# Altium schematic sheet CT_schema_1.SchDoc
size 532 x 463 mm
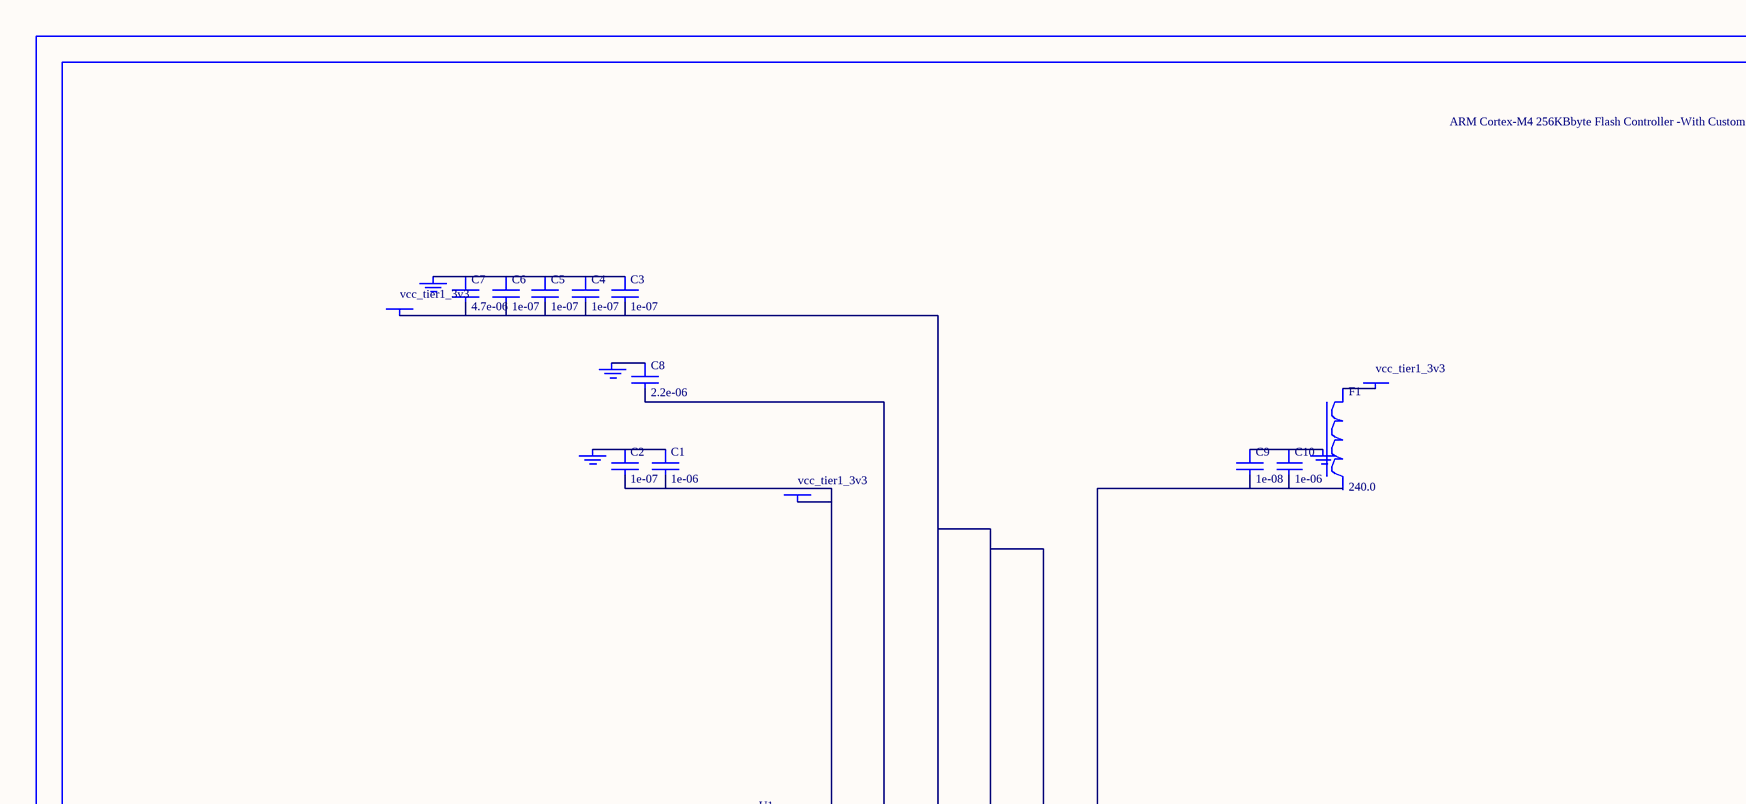
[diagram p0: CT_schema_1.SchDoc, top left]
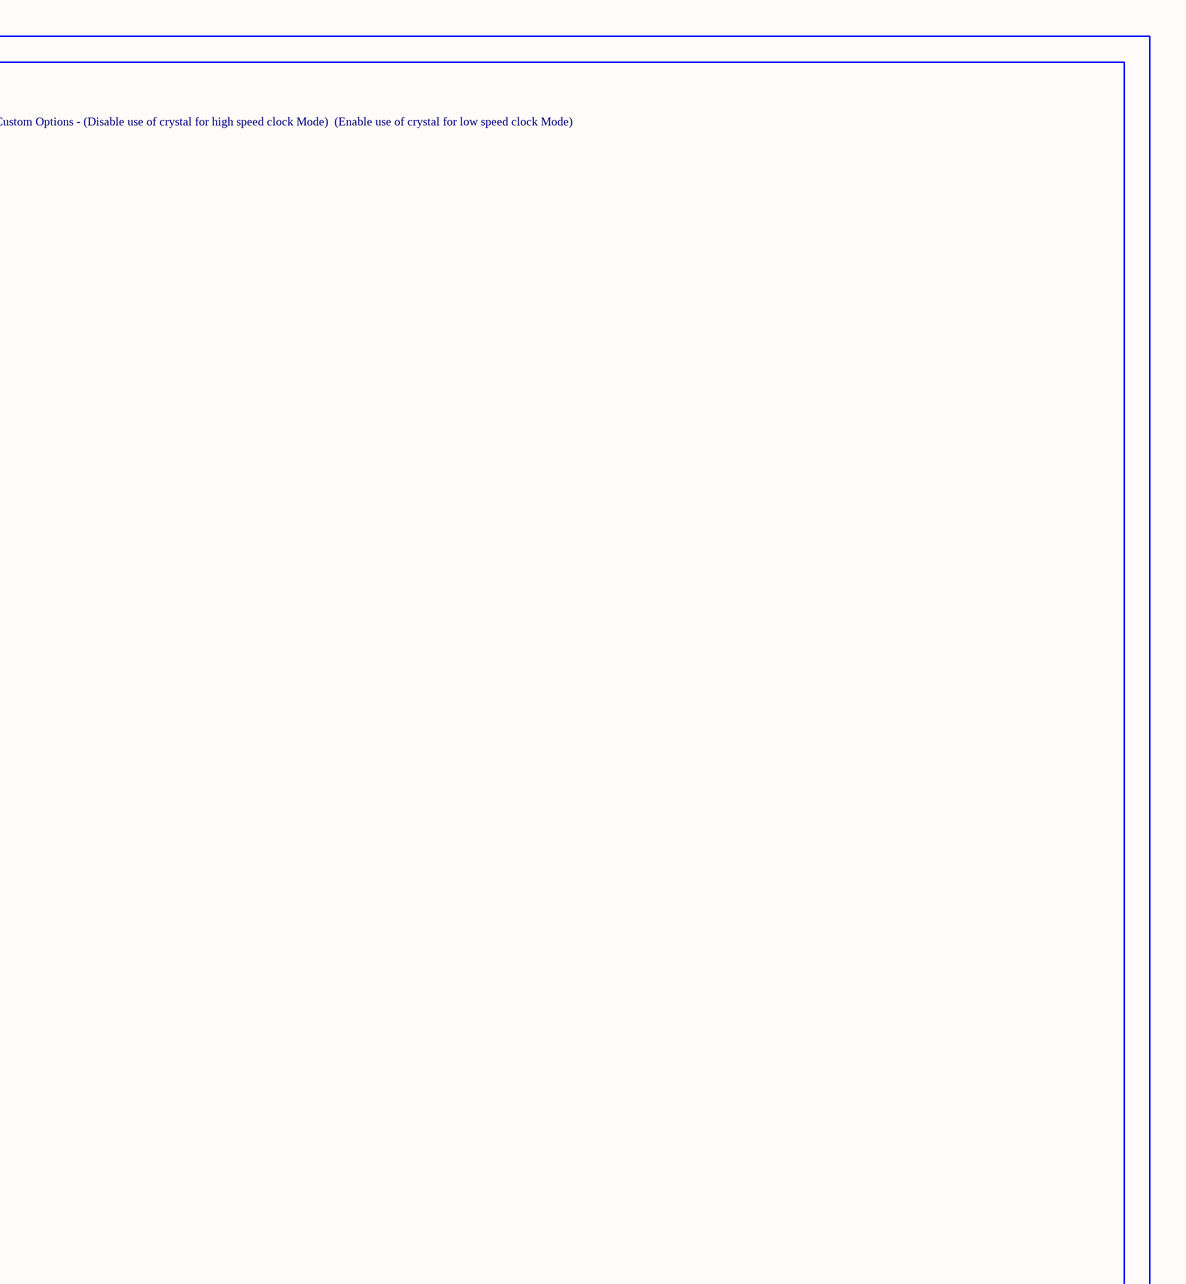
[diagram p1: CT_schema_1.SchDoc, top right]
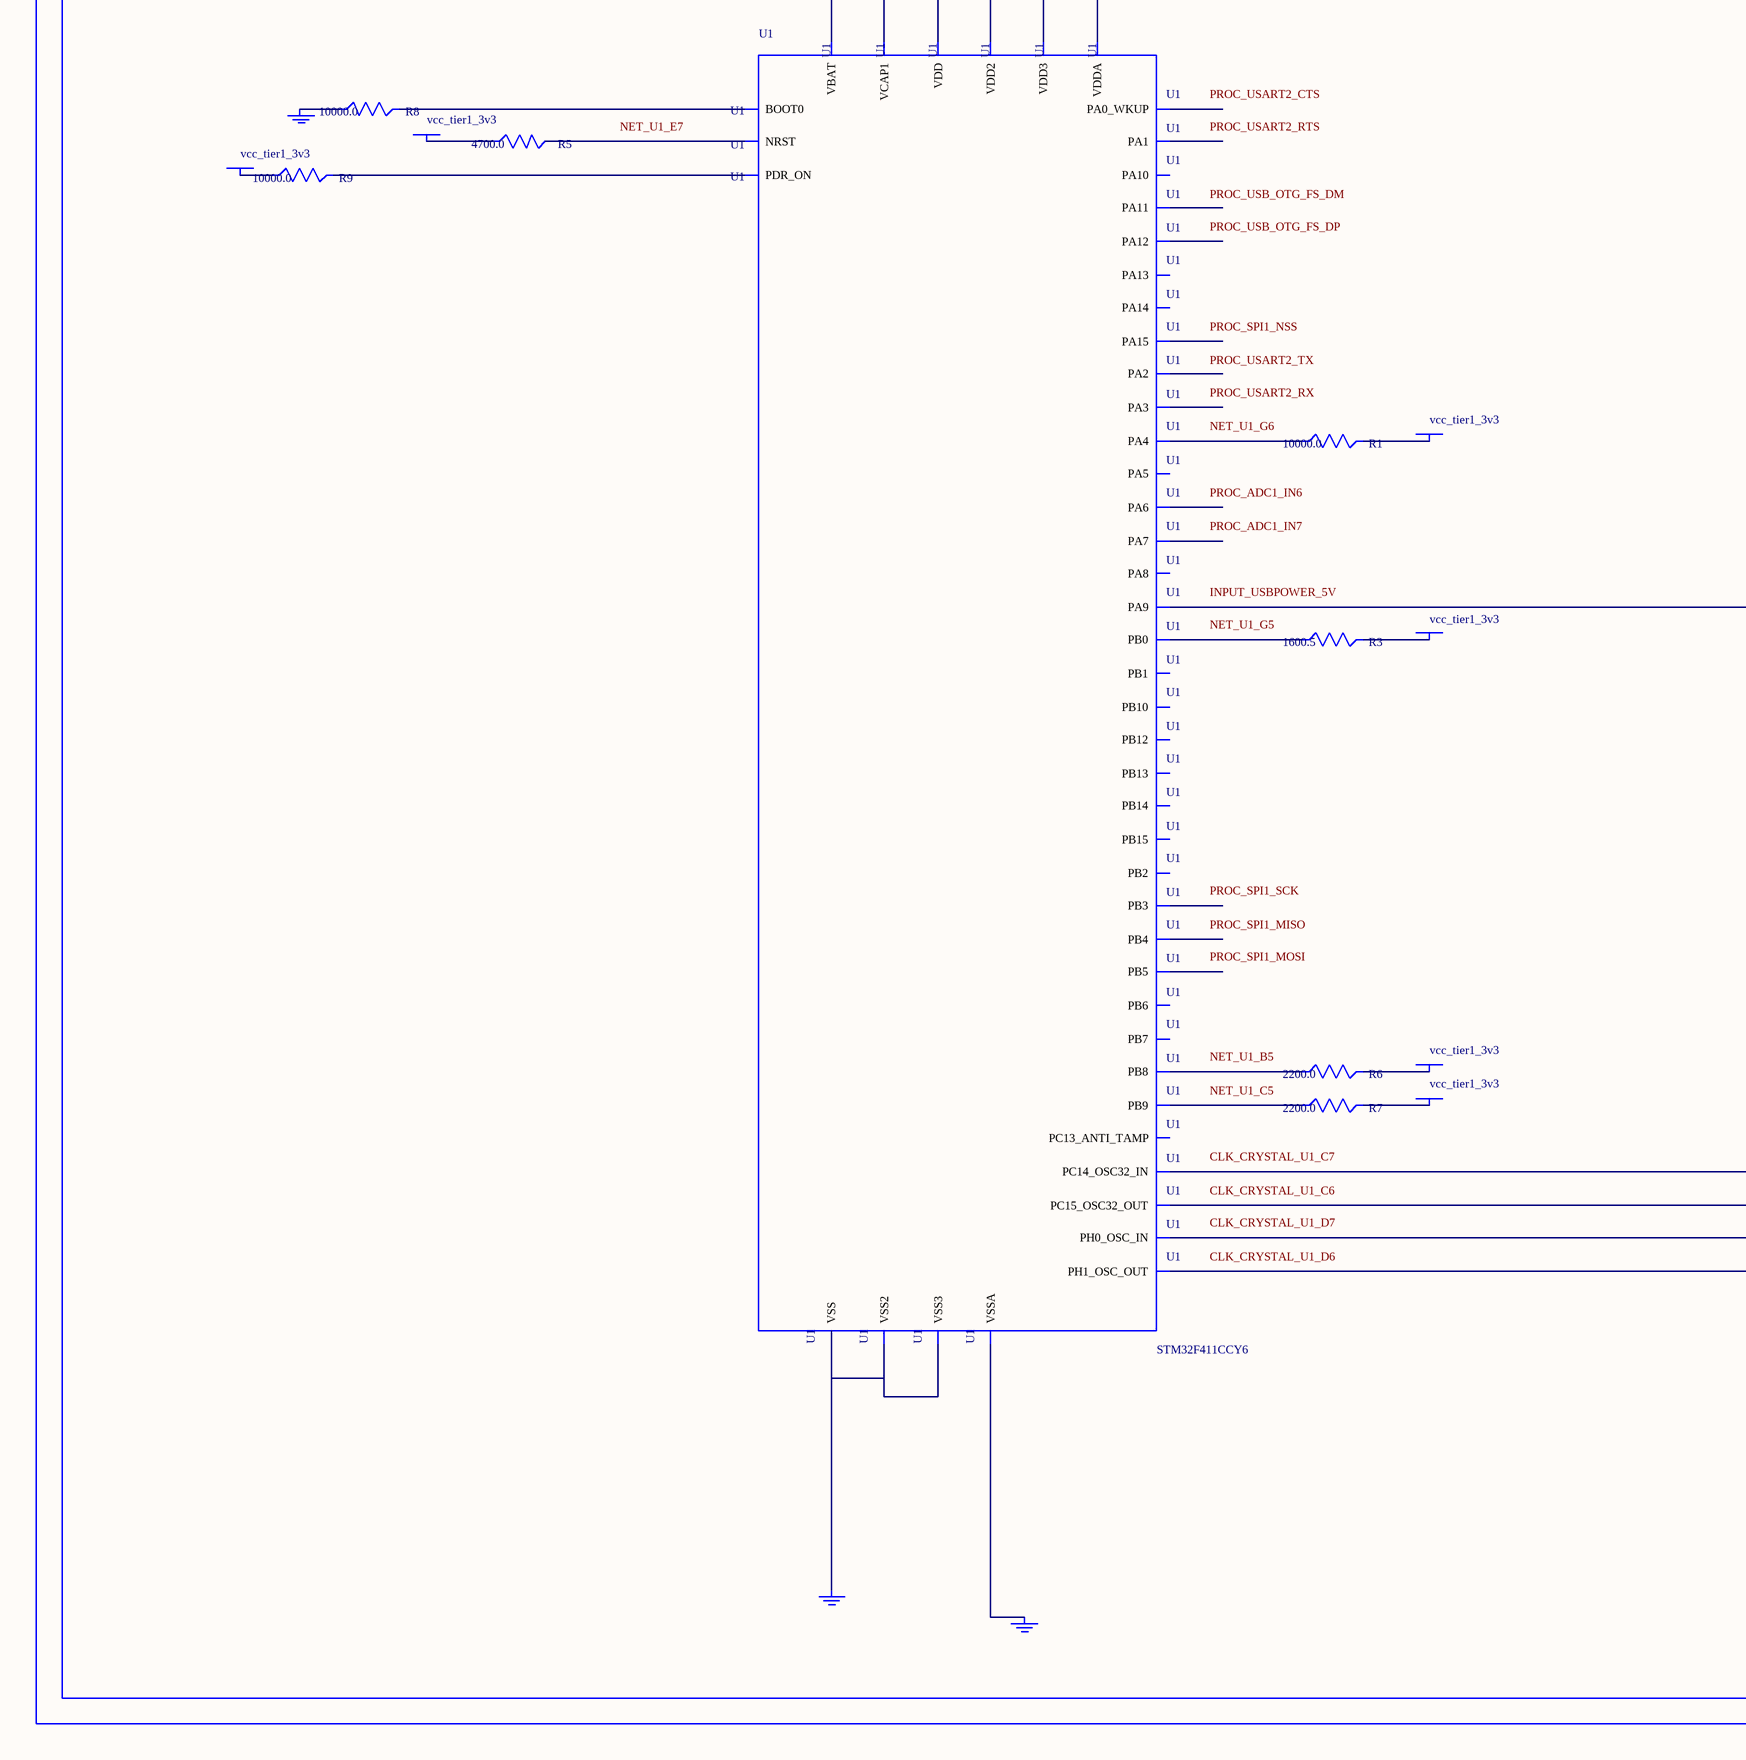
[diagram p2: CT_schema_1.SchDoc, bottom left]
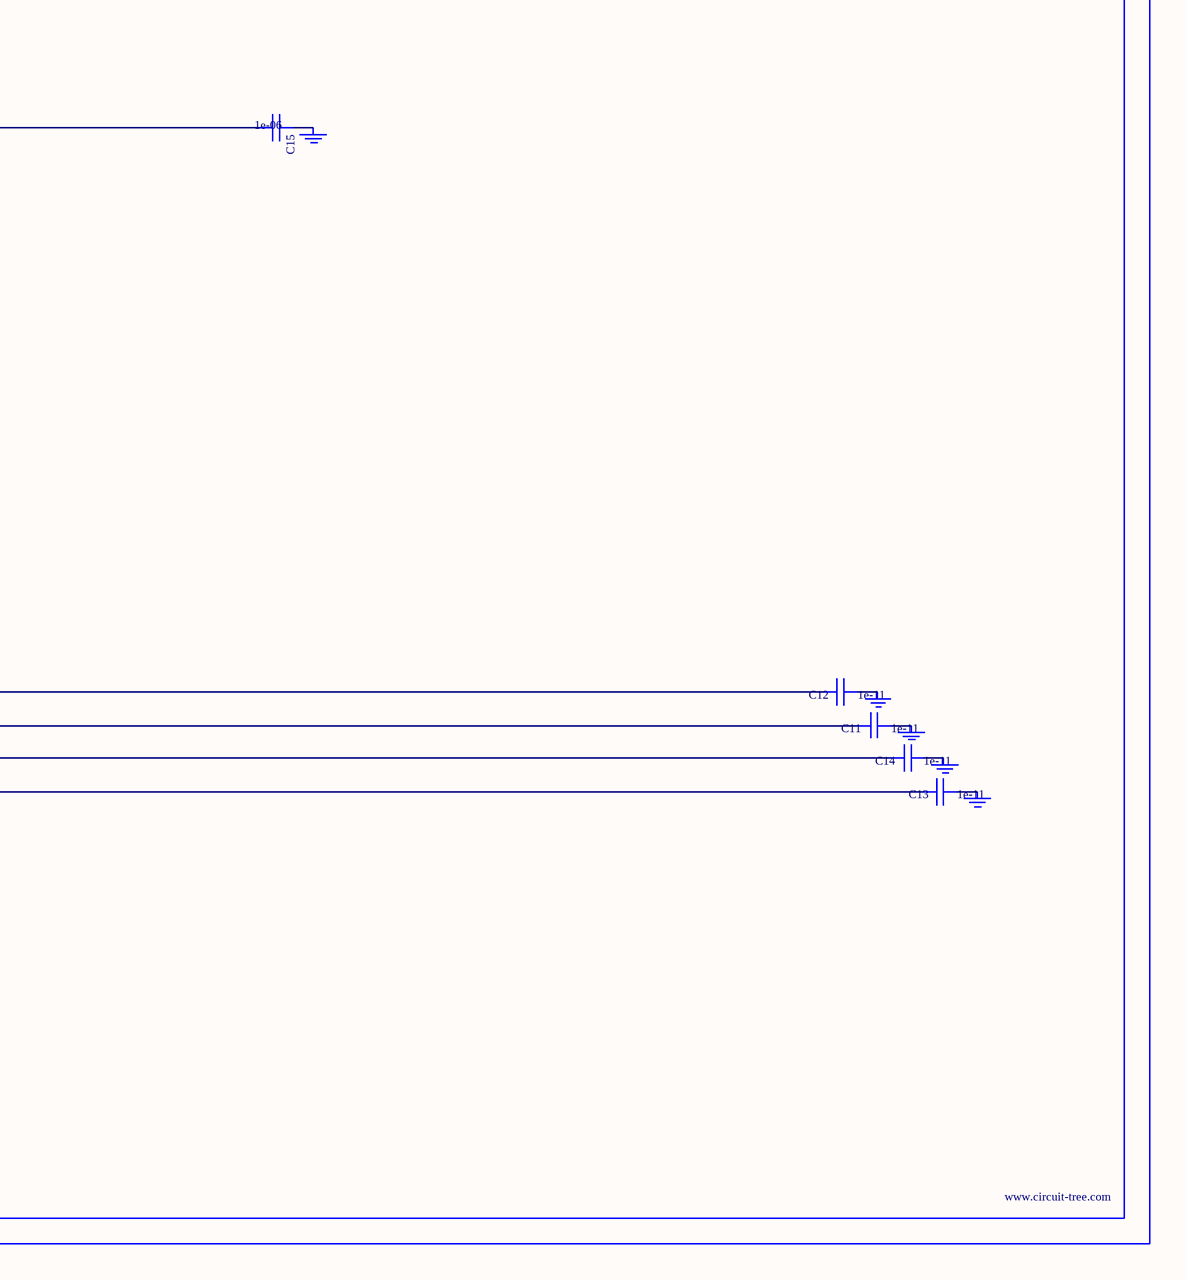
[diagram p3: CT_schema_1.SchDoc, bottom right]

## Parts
BORDER0  (no value)
C1  1e-06  [C0603]
C2  1e-07  [C0603]
C3  1e-07  [C0603]
C4  1e-07  [C0603]
C5  1e-07  [C0603]
C6  1e-07  [C0603]
C7  4.7e-06  [C0603]
C8  2.2e-06  [C0603]
C9  1e-08  [C0603]
C10  1e-06  [C0603]
C11  1e-11  [C0402]
C12  1e-11  [C0402]
C13  1e-11  [C0402]
C14  1e-11  [C0402]
C15  1e-06  [C0603]
F1  240.0  [L0603]
GND_INSTANCE_0_0  (no value)
GND_INSTANCE_0_1  (no value)
GND_INSTANCE_0_2  (no value)
GND_INSTANCE_0_3  (no value)
GND_INSTANCE_0_4  (no value)
GND_INSTANCE_0_5  (no value)
GND_INSTANCE_0_6  (no value)
GND_INSTANCE_0_7  (no value)
GND_INSTANCE_0_8  (no value)
GND_INSTANCE_0_9  (no value)
GND_INSTANCE_0_10  (no value)
GND_INSTANCE_0_11  (no value)
POWER_INSTANCE_0_0  vcc_tier1_3v3
POWER_INSTANCE_0_1  vcc_tier1_3v3
POWER_INSTANCE_0_2  vcc_tier1_3v3
POWER_INSTANCE_0_3  vcc_tier1_3v3
POWER_INSTANCE_0_4  vcc_tier1_3v3
POWER_INSTANCE_0_5  vcc_tier1_3v3
POWER_INSTANCE_0_6  vcc_tier1_3v3
POWER_INSTANCE_0_7  vcc_tier1_3v3
POWER_INSTANCE_0_8  vcc_tier1_3v3
R1  10000.0  [R0603]
R3  1600.5  [R0603]
R5  4700.0  [R0603]
R6  2200.0  [R0603]
R7  2200.0  [R0603]
R8  10000.0  [R0603]
R9  10000.0  [R0603]
U1  STM32F411CCY6  [WLCSP49]

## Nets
NetC1_1: C1.1 C2.1 GND_INSTANCE_0_0.0(GND)
NetC1_2: C1.2 C2.2 POWER_INSTANCE_0_0.0(PWR) U1.B7(VBAT)
NetC3_1: C3.1 C4.1 C5.1 C6.1 C7.1 GND_INSTANCE_0_2.0(GND)
NetC3_2: C3.2 C4.2 C5.2 C6.2 C7.2 POWER_INSTANCE_0_2.0(PWR) U1.A7(VDD) U1.B2(VDD2) U1.F2(VDD3)
NetC8_1: C8.1 GND_INSTANCE_0_4.0(GND)
NetC8_2: C8.2 U1.G2(VCAP1)
NetC9_1: C9.1 C10.1 GND_INSTANCE_0_1.0(GND)
NetC9_2: C9.2 C10.2 U1.F7(VDDA)
NetC11_1: C11.1 GND_INSTANCE_0_5.0(GND)
NetC11_2: C11.2 U1.C6(PC15_OSC32_OUT)
NetC12_1: C12.1 GND_INSTANCE_0_6.0(GND)
NetC12_2: C12.2 U1.C7(PC14_OSC32_IN)
NetC13_1: C13.1 GND_INSTANCE_0_7.0(GND)
NetC13_2: C13.2 U1.D6(PH1_OSC_OUT)
NetC14_1: C14.1 GND_INSTANCE_0_8.0(GND)
NetC14_2: C14.2 U1.D7(PH0_OSC_IN)
NetC15_1: C15.1 GND_INSTANCE_0_9.0(GND)
NetC15_2: C15.2 U1.D2(PA9)
NetF1_1: F1.1 POWER_INSTANCE_0_1.0(PWR)
NetGND_INSTANCE_0_3_0: GND_INSTANCE_0_3.0(GND) R8.1
NetGND_INSTANCE_0_10_0: GND_INSTANCE_0_10.0(GND) U1.E6(VSSA)
NetGND_INSTANCE_0_11_0: GND_INSTANCE_0_11.0(GND) U1.A6(VSS) U1.B1(VSS2) U1.D3(VSS3)
NetPOWER_INSTANCE_0_3_0: POWER_INSTANCE_0_3.0(PWR) R9.1
NetPOWER_INSTANCE_0_4_0: POWER_INSTANCE_0_4.0(PWR) R5.1
NetPOWER_INSTANCE_0_5_0: POWER_INSTANCE_0_5.0(PWR) R1.2
NetPOWER_INSTANCE_0_6_0: POWER_INSTANCE_0_6.0(PWR) R3.2
NetPOWER_INSTANCE_0_7_0: POWER_INSTANCE_0_7.0(PWR) R6.2
NetPOWER_INSTANCE_0_8_0: POWER_INSTANCE_0_8.0(PWR) R7.2
NetR1_1: R1.1 U1.G6(PA4)
NetR3_1: R3.1 U1.G5(PB0)
NetR5_2: R5.2 U1.E7(NRST)
NetR6_1: R6.1 U1.B5(PB8)
NetR7_1: R7.1 U1.C5(PB9)
NetR8_2: R8.2 U1.A5(BOOT0)
NetR9_2: R9.2 U1.B6(PDR_ON)

Not connected (* = marked no-connect by the designer): F1 2; U1 A1(PA14) A2(PA15) A3(PB3) A4(PB4) B3(PA13) B4(PB5) C1(PA11) C2(PA10) C3(PA12) C4(PB6) D1(PA8) D4(PB7) D5(PC13_ANTI_TAMP) E1(PB15) E2(PB12) E3(PB10) E4(PA3) E5(PA2) F1(PB14) F3(PA7) F4(PA6) F5(PA5) F6(PA0_WKUP) G1(PB13) G3(PB2) G4(PB1) G7(PA1)

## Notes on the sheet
- Labels drawn without touching a wire or pin: CLK_CRYSTAL_U1_C6, CLK_CRYSTAL_U1_C7, CLK_CRYSTAL_U1_D6, CLK_CRYSTAL_U1_D7, INPUT_USBPOWER_5V, NET_U1_B5, NET_U1_C5, NET_U1_E7, NET_U1_G5, NET_U1_G6, PROC_ADC1_IN6, PROC_ADC1_IN7, PROC_SPI1_MISO, PROC_SPI1_MOSI, PROC_SPI1_NSS, PROC_SPI1_SCK, PROC_USART2_CTS, PROC_USART2_RTS, PROC_USART2_RX, PROC_USART2_TX, PROC_USB_OTG_FS_DM, PROC_USB_OTG_FS_DP

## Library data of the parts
BORDER0 = BORDER_PAGE0
C1 C10 C15 = C0603C105K3RACTU
C2-C6 = 06035C104K4Z2A
C7 = GRM188R6YA475KE15D
C8 = C0603C225K8RACTU
C9 = 06035C103K4Z2A
C11-C14 = C0402C100K3GACTU
F1 = Z0603C241ASMST
GND_INSTANCE_0_0-GND_INSTANCE_0_11 = GND
POWER_INSTANCE_0_0-POWER_INSTANCE_0_8 = PWR
R1 R8 R9 = RC0603JR-0710KL
R3 = R3
R5 = RC0603JR-074K7L
R6 R7 = RC0603JR-072K2L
